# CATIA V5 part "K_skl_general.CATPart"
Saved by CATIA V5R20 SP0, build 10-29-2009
Part number: skl_general
Publications: "decalage pneu", "ecart branches tandem", "axe 3/18 y", "axe 3/10 y", "axe 24/33 y", "axe 24/28 y", "axe 10/17 y", "axe 10/17 z", "axe 10/23 y", "axe 10/23 z", "epaisseur pieces", "axe 10/21 y", "axe 10/21 z", "epaisseur verin de commande", "axe 21/74 y", "axe 21/74 z", "reference", "axe 21/28 y", "axe 21/28 z", "axe 28/29 y", "axe 28/29 z", "axe 28/38 y", "axe 28/38 z", "axe 51/50 y", "axe 51/50 z", "axe 51/38 y", "axe 51/38 z", "axe 51/70 y", "axe 51/70 z", "axe 57/38 y", "axe 57/38 z", "axe 57/50 y", "axe 57/50 z", "longueur amortisseur", "longueur tige", "longueur verin commande", "Plan.00", "Plan.+100", "Plan.-30", "Plan.-45", "Plan.-55", "Plan.-100", "pneu 5", "pneu 25", "liaison 3/18 sur 3", "liaison 3/18 sur 18", "liaison 3/10", "liaison 3/5", "liaison 24/25", "liaison 24/33 sur 24", "liaison 24/33 sur 33", "liaison 24/28", "liaison 10/17 sur 10", "liaison 10/17 sur 17", "liaison 10/23 sur 10", "liaison 10/23 sur 23", "liaison 10/21", "liaison 21/74 sur 21", "liaison 21/74 sur 74", "liaison 21/28", "liaison 28/29 sur 28", "liaison 28/29 sur 29", "liaison 28/38", "liaison 51/50", "liaison 51/38", "liaison 51/70 sur 51", "liaison 51/70 sur 70", "liaison 57/38", "liaison 57/50", "liaison avion 3/10", "liaison avion 24/28", "droite appui verin gauche", "droite appui verin droite", "droite appui verin commande", "longueur axe pivot", "Plan.+30", "liaison 28/38 sur 38", "liaison 38/51 sur 38", "liaison 23/57/38 sur 38", "rayon 25mm", "rayon pneu", "largeur pneu", "rayon congé", "demi largeur balancier", "demi largeur tige"
Bounding box of the stored display mesh (mm): x -100 to 100, y -990 to 1060, z -55 to 795
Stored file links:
  G:\Khaled_CFAO_2011\SIL\SIL_GR2\mdardier\Khaled\CAD_ThinkMOTION\K_skl_general.CATPart
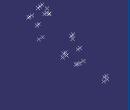
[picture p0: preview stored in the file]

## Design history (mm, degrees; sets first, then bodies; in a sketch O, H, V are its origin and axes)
Parameters
  `decalage pneu` = 100 mm
  `ecart branches tandem` = 1060 mm
  `axe 3/18 y` = -85 mm
  `axe 3/10 y` = -720 mm
  `axe 24/33 y` = 975 mm
  `axe 24/28 y` = 340 mm
  `axe 10/17 y` = -775 mm
  `axe 10/17 z` = 285 mm
  `axe 10/23 y` = -990 mm
  `axe 10/23 z` = 360 mm
  `epaisseur pieces` = 30 mm
  `axe 10/21 y` = -910 mm
  `axe 10/21 z` = 445 mm
  `axe 21/74 y` = 115 mm
  `axe 21/74 z` = 500 mm
  reference = 0 mm
  `axe 21/28 y` = 150 mm
  `axe 21/28 z` = 445 mm
  `axe 28/29 y` = 285 mm
  `axe 28/29 z` = 285 mm
  `axe 28/38 y` = 275 mm
  `axe 28/38 z` = -55 mm
  `axe 51/50 y` = -545 mm
  `axe 51/50 z` = 765 mm
  `axe 51/38 y` = -550 mm
  `axe 51/38 z` = 670 mm
  `axe 51/70 y` = -495 mm
  `axe 51/70 z` = 665 mm
  `axe 57/23 y` = -720 mm
  `axe 57/23 z` = 725 mm
  `axe 57/50 y` = -660 mm
  `axe 57/50 z` = 795 mm
  `longueur amortisseur` = 410 mm
  `longueur tige` = 550 mm
  `longueur verin commande` = 620 mm
  `longueur axe pivot` = 150 mm
  `rayon pneu` = 240 mm
  `largeur pneu` = 200 mm
  `rayon congé` = 20 mm
  `demi largeur balancier` = 50 mm
  `demi largeur tige` = 17.5 mm
Set1
  Plane1 "Plan.00": type Offset, RefPlane yz-plane, Offset 0 {= reference}
  Plane2 "Plan.+100": type Offset, RefPlane yz-plane, Offset 100 {= `decalage pneu`}
  Plane3 "Plan.-30": type Offset, RefPlane yz-plane, Offset -30
  Plane4 "Plan.-55": type Offset, RefPlane yz-plane, Offset -55 {= -`epaisseur pieces` -`demi largeur balancier` /2}
  Plane5 "Plan.-100": type Offset, RefPlane yz-plane, Offset -100 {= -`decalage pneu`}
  Point1 "pneu 5": (100 {= `decalage pneu`}, 0 {= reference}, 0 {= reference})
  Point2 "pneu 25": (100 {= `decalage pneu`}, 1060 {= `ecart branches tandem`}, 0 {= reference})
  Point3 "liaison 3/18 sur 3": (0 {= reference}, -85 {= `axe 3/18 y`}, 0 {= reference})
  Point4 "liaison 3/18 sur 18": (-55 {= -`epaisseur pieces` -`demi largeur balancier` /2}, -85 {= `axe 3/18 y`}, 0 {= reference})
  Point5 "liaison 3/10": (0 {= reference}, -720 {= `axe 3/10 y`}, 0 {= reference})
  Point6 "liaison 3/5": (0 {= reference}, 0 {= reference}, 0 {= reference})
  Point7 "liaison 24/25": (0 {= reference}, 1060 {= `ecart branches tandem`}, 0 {= reference})
  Point8 "liaison 24/33 sur 24": (0 {= reference}, 975 {= `axe 24/33 y`}, 0 {= reference})
  Point9 "liaison 24/33 sur 33": (-55 {= -`epaisseur pieces` -`demi largeur balancier` /2}, 975 {= `axe 24/33 y`}, 0 {= reference})
  Point10 "liaison 24/28": (0 {= reference}, 340 {= `axe 24/28 y`}, 0 {= reference})
  Point11 "liaison 10/17 sur 10": (0 {= reference}, -775 {= `axe 10/17 y`}, 285 {= `axe 10/17 z`})
  Point12 "liaison 10/17 sur 17": (-55 {= -`epaisseur pieces` -`demi largeur balancier` /2}, -775 {= `axe 10/17 y`}, 285 {= `axe 10/17 z`})
  Point13 "liaison 10/23 sur 10": (0 {= reference}, -990 {= `axe 10/23 y`}, 360 {= `axe 10/23 z`})
  Point14 "liaison 10/23 sur 23": (-30 {= -`epaisseur pieces`}, -990 {= `axe 10/23 y`}, 360 {= `axe 10/23 z`})
  Point15 "liaison 10/21": (0 {= reference}, -910 {= `axe 10/21 y`}, 445 {= `axe 10/21 z`})
  Point16 "liaison 21/74 sur 21": (0 {= reference}, 115 {= `axe 21/74 y`}, 500 {= `axe 21/74 z`})
  Point17 "liaison 21/74 sur 74": (-55 {= -`epaisseur pieces` -`demi largeur balancier` /2}, 115 {= `axe 21/74 y`}, 500 {= `axe 21/74 z`})
  Point18 "liaison 21/28": (0 {= reference}, 150 {= `axe 21/28 y`}, 445 {= `axe 21/28 z`})
  Point19 "liaison 28/29 sur 28": (0 {= reference}, 285 {= `axe 28/29 y`}, 285 {= `axe 28/29 z`})
  Point20 "liaison 28/29 sur 29": (-55 {= -`epaisseur pieces` -`demi largeur balancier` /2}, 285 {= `axe 28/29 y`}, 285 {= `axe 28/29 z`})
  Point21 "liaison 28/38 sur 28": (0 {= reference}, 275 {= `axe 28/38 y`}, -55 {= `axe 28/38 z`})
  Point22 "liaison 51/50": (-30 {= -`epaisseur pieces`}, -545 {= `axe 51/50 y`}, 765 {= `axe 51/50 z`})
  Point23 "liaison 51/38 sur 51": (-30 {= -`epaisseur pieces`}, -550 {= `axe 51/38 y`}, 670 {= `axe 51/38 z`})
  Point24 "liaison 51/70 sur 51": (-30 {= -`epaisseur pieces`}, -495 {= `axe 51/70 y`}, 665 {= `axe 51/70 z`})
  Point25 "liaison 51/70 sur 70": (-55 {= -`epaisseur pieces` -`demi largeur balancier` /2}, -495 {= `axe 51/70 y`}, 665 {= `axe 51/70 z`})
  Point26 "liaison 57/23": (-30 {= -`epaisseur pieces`}, -720 {= `axe 57/23 y`}, 725 {= `axe 57/23 z`})
  Point27 "liaison 57/50": (-30 {= -`epaisseur pieces`}, -660 {= `axe 57/50 y`}, 795 {= `axe 57/50 z`})
  Point28 "liaison avion 3/10": (-100 {= -`decalage pneu`}, -720 {= `axe 3/10 y`}, 0 {= reference})
  Point29 "liaison avion 24/28": (-100 {= -`decalage pneu`}, 340 {= `axe 24/28 y`}, 0 {= reference})
  Line1 "droite appui verin gauche": type PtPt, FirstPoint Point12, SecondPoint Point4
  Line2 "droite appui verin droite": type PtPt, FirstPoint Point20, SecondPoint Point9
  Line3 "droite appui verin commande": type PtPt, FirstPoint Point25, SecondPoint Point17
  Plane6 "Plan.+30": type Offset, RefPlane yz-plane, Offset 30 {= `epaisseur pieces`}
  Point30 "liaison 28/38 sur 38": (30 {= `epaisseur pieces`}, 275 {= `axe 28/38 y`}, -55 {= `axe 28/38 z`})
  Point31 "liaison 38/51 sur 38": (30 {= `epaisseur pieces`}, -550 {= `axe 51/38 y`}, 670 {= `axe 51/38 z`})
  Point32 "liaison 23/57/38 sur 38": (30 {= `epaisseur pieces`}, -720 {= `axe 57/23 y`}, 725 {= `axe 57/23 z`})
Body1 (main body)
